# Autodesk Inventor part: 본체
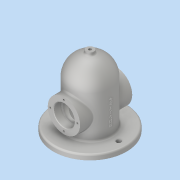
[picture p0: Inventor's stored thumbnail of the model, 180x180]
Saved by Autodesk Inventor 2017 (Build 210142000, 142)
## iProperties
Created: 2019-11
Part Number: 본체
Material: Aluminum 6061
Document SubType Name: Modeling
Designer: 1-17-lg
Density: 2.7 g/cm^3
Appearance: Aluminum - Flat
Mass: 1106.12 g
Surface Area: 883.263 cm^2
Volume: 409.676 cm^3
Author: 1-17-lg
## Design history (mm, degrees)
sketch "Sketch2"
  geometry: C1 r 70 at (0, 0); 1 further point
  constraints: 1 centre point, 1 coincident
  dimensions: "d0" = 140 diameter of C1
extrude "Extrusion1" new body sketch "Sketch2" distance "d1" = 10; taper "d2" = 0 deg
sketch "Sketch4"
  geometry: L1 (0, 90)-(40, 90); L2 (40, 90)-(40, 0); L3 (-70, 0)-(70, 0) reference; L4 (0, 0)-(40, 0); L5 (0, 0)-(0, 130); A1 r 40 centre (0, 90) between (40, 90) and (0, 130)
  constraints: 8 end point, 2 perpendicular, 2 point on circle, 1 centre point, 1 point on line, 1 vertical
  dimensions: "d4" = 90 distance of L4.start L1.start; "d5" = 40 distance of L1.end L1.start
revolve "Revolution1" sketch "Sketch4" stored, may be unused: angle "d6" = 90 deg
workplane "Work Plane1"
sketch "Sketch5"
  geometry: C1 r 7.5 at (0, 0); 1 further point
  constraints: 1 centre point, 1 coincident
  dimensions: "d8" = 15 diameter of C1
extrude "Extrusion2" join sketch "Sketch5" stored distance "d9" = 10; taper "d10" = 0 deg
sketch "Sketch7"
  geometry: L1 (0, 0)-(0, 50); C1 r 31 at (0, 50)
  constraints: 2 end point, 1 centre point, 1 coincident, 1 vertical
  dimensions: "d14" = 50 distance of L1.start L1.end; "d15" = 62 diameter of C1
extrude "Extrusion3" join sketch "Sketch7" stored distance "d16" = 100; taper "d17" = 0 deg
sketch "Sketch8"
  geometry: L1 (0, 90)-(30, 90); L2 (30, 90)-(30, 0); L3 (30, 0)-(0, 0); L4 (0, 0)-(0, 120); A1 r 30 centre (0, 90) between (30, 90) and (0, 120)
  constraints: 8 end point, 2 perpendicular, 2 point on circle, 1 centre point, 1 coincident, 1 vertical
  dimensions: "d19" = 30 distance of L1.end L1.start
revolve "Revolution3" sketch "Sketch8" stored, may be unused: angle "d20" = 90 deg
sketch "Sketch11"
  geometry: C1 r 31 at (0, 0) reference; C2 r 16.5 at (0, 0); 1 further point
  constraints: 1 centre point, 1 coincident
  dimensions: "d21" = 33 diameter of C2
extrude "Extrusion4" cut sketch "Sketch11" stored distance "d22" = 100; taper "d23" = 0 deg
sketch "Sketch12"
  geometry: C1 r 31 at (0, 0) reference; C2 r 20 at (0, 0); 1 further point
  constraints: 1 centre point, 1 coincident
  dimensions: "d24" = 40 diameter of C2
extrude "Extrusion5" cut sketch "Sketch12" distance "d25" = 15; taper "d26" = 0 deg
mirror "Mirror1"
sketch "Sketch13"
  geometry: C1 r 7.5 at (0, 0) reference; 1 further point
  constraints: 1 coincident
hole "Hole1" sketch "Sketch13" at (0, 0) diameter "d27" = 5.188; stored, may be unused: countersink angle "d31" = 90 deg, drill point angle "d33" = 118 deg; dims "d28" = 12, "d29" = 4, "d30" = 2, "d32" = 16
sketch "Sketch14" dims "d34" = 52
  geometry: L1 (0, 0)-(0, 26); C1 r 31 at (0, 0) reference; 2 further points
  constraints: 2 coincident, 2 end point, 1 vertical, 1 vertical alignment, 2 other
hole "Hole2" sketch "Sketch14" at (0, 26) diameter "d35" = 3.242; stored, may be unused: countersink angle "d39" = 90 deg, drill point angle "d41" = 118 deg; dims "d36" = 8, "d37" = 4, "d38" = 2, "d40" = 10
pattern_circular "Circular Pattern1" dims angle "d43" = 360 deg
mirror "Mirror2"
sketch "Sketch15"
  geometry: L1 (-55, 0)-(55, 0); C1 r 7.5 at (0, 0) reference; C2 r 4.5 at (-55, 0); C3 r 4.5 at (55, 0); A1 r 55 centre (0, 0) between (-55, 0) and (55, 0)
  constraints: 3 centre point, 3 coincident, 2 end point, 2 point on circle
  dimensions: "d45" = 110 diameter of A1; "d46" = 9 diameter of C2; "d47" = 9 diameter of C3
extrude "Extrusion6" cut sketch "Sketch15" stored distance "d48" = 15; taper "d49" = 0 deg
workplane "Work Plane2"
sketch "Sketch16"
  geometry: L1 (53.715, 39.975)-(53.055, -40.025); L2 (53.055, -40.025)-(46.945, -39.975); L3 (46.945, -39.975)-(47.605, 40.025); L4 (47.605, 40.025)-(53.715, 39.975); L5 (0, 0)-(50.33, 0); L6 (50, -40)-(50.66, 40); L7 (53.385, -0.025)-(47.275, 0.025); L8 (90, -40)-(10, -40) reference; L9 (90, 40)-(10, 40) reference
  constraints: 6 end point, 6 midpoint, 1 horizontal, 2 other
  dimensions: "d51" = 50.33 distance of L5.end L5.start
emboss "Emboss1" sketch "Sketch16" dims "d52" = 0.5, "d53" = 0
fillet "Fillet1" dims "d54" = 3, "d55" = 0.3
chamfer "Chamfer1" distance "d56" = 1; stored, may be unused: second distance "d57" = 2, angle "d58" = 45 deg
chamfer "Chamfer2" distance "d59" = 1; stored, may be unused: second distance "d60" = 2, angle "d61" = 45 deg
body "Solid1"
other parameters: "d7" = 135
